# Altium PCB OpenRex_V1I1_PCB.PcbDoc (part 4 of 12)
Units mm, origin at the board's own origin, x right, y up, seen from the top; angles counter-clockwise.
Board outline 70 x 95 mm, 10 copper layers (L1, L2, L3, L4 (PWR), L5 (PWR), L6 (PWR), L7 (PWR), L8, L9, L10), stack 1.632 mm thick; 1080 components, 708 nets, 3831 pads, 2373 vias.
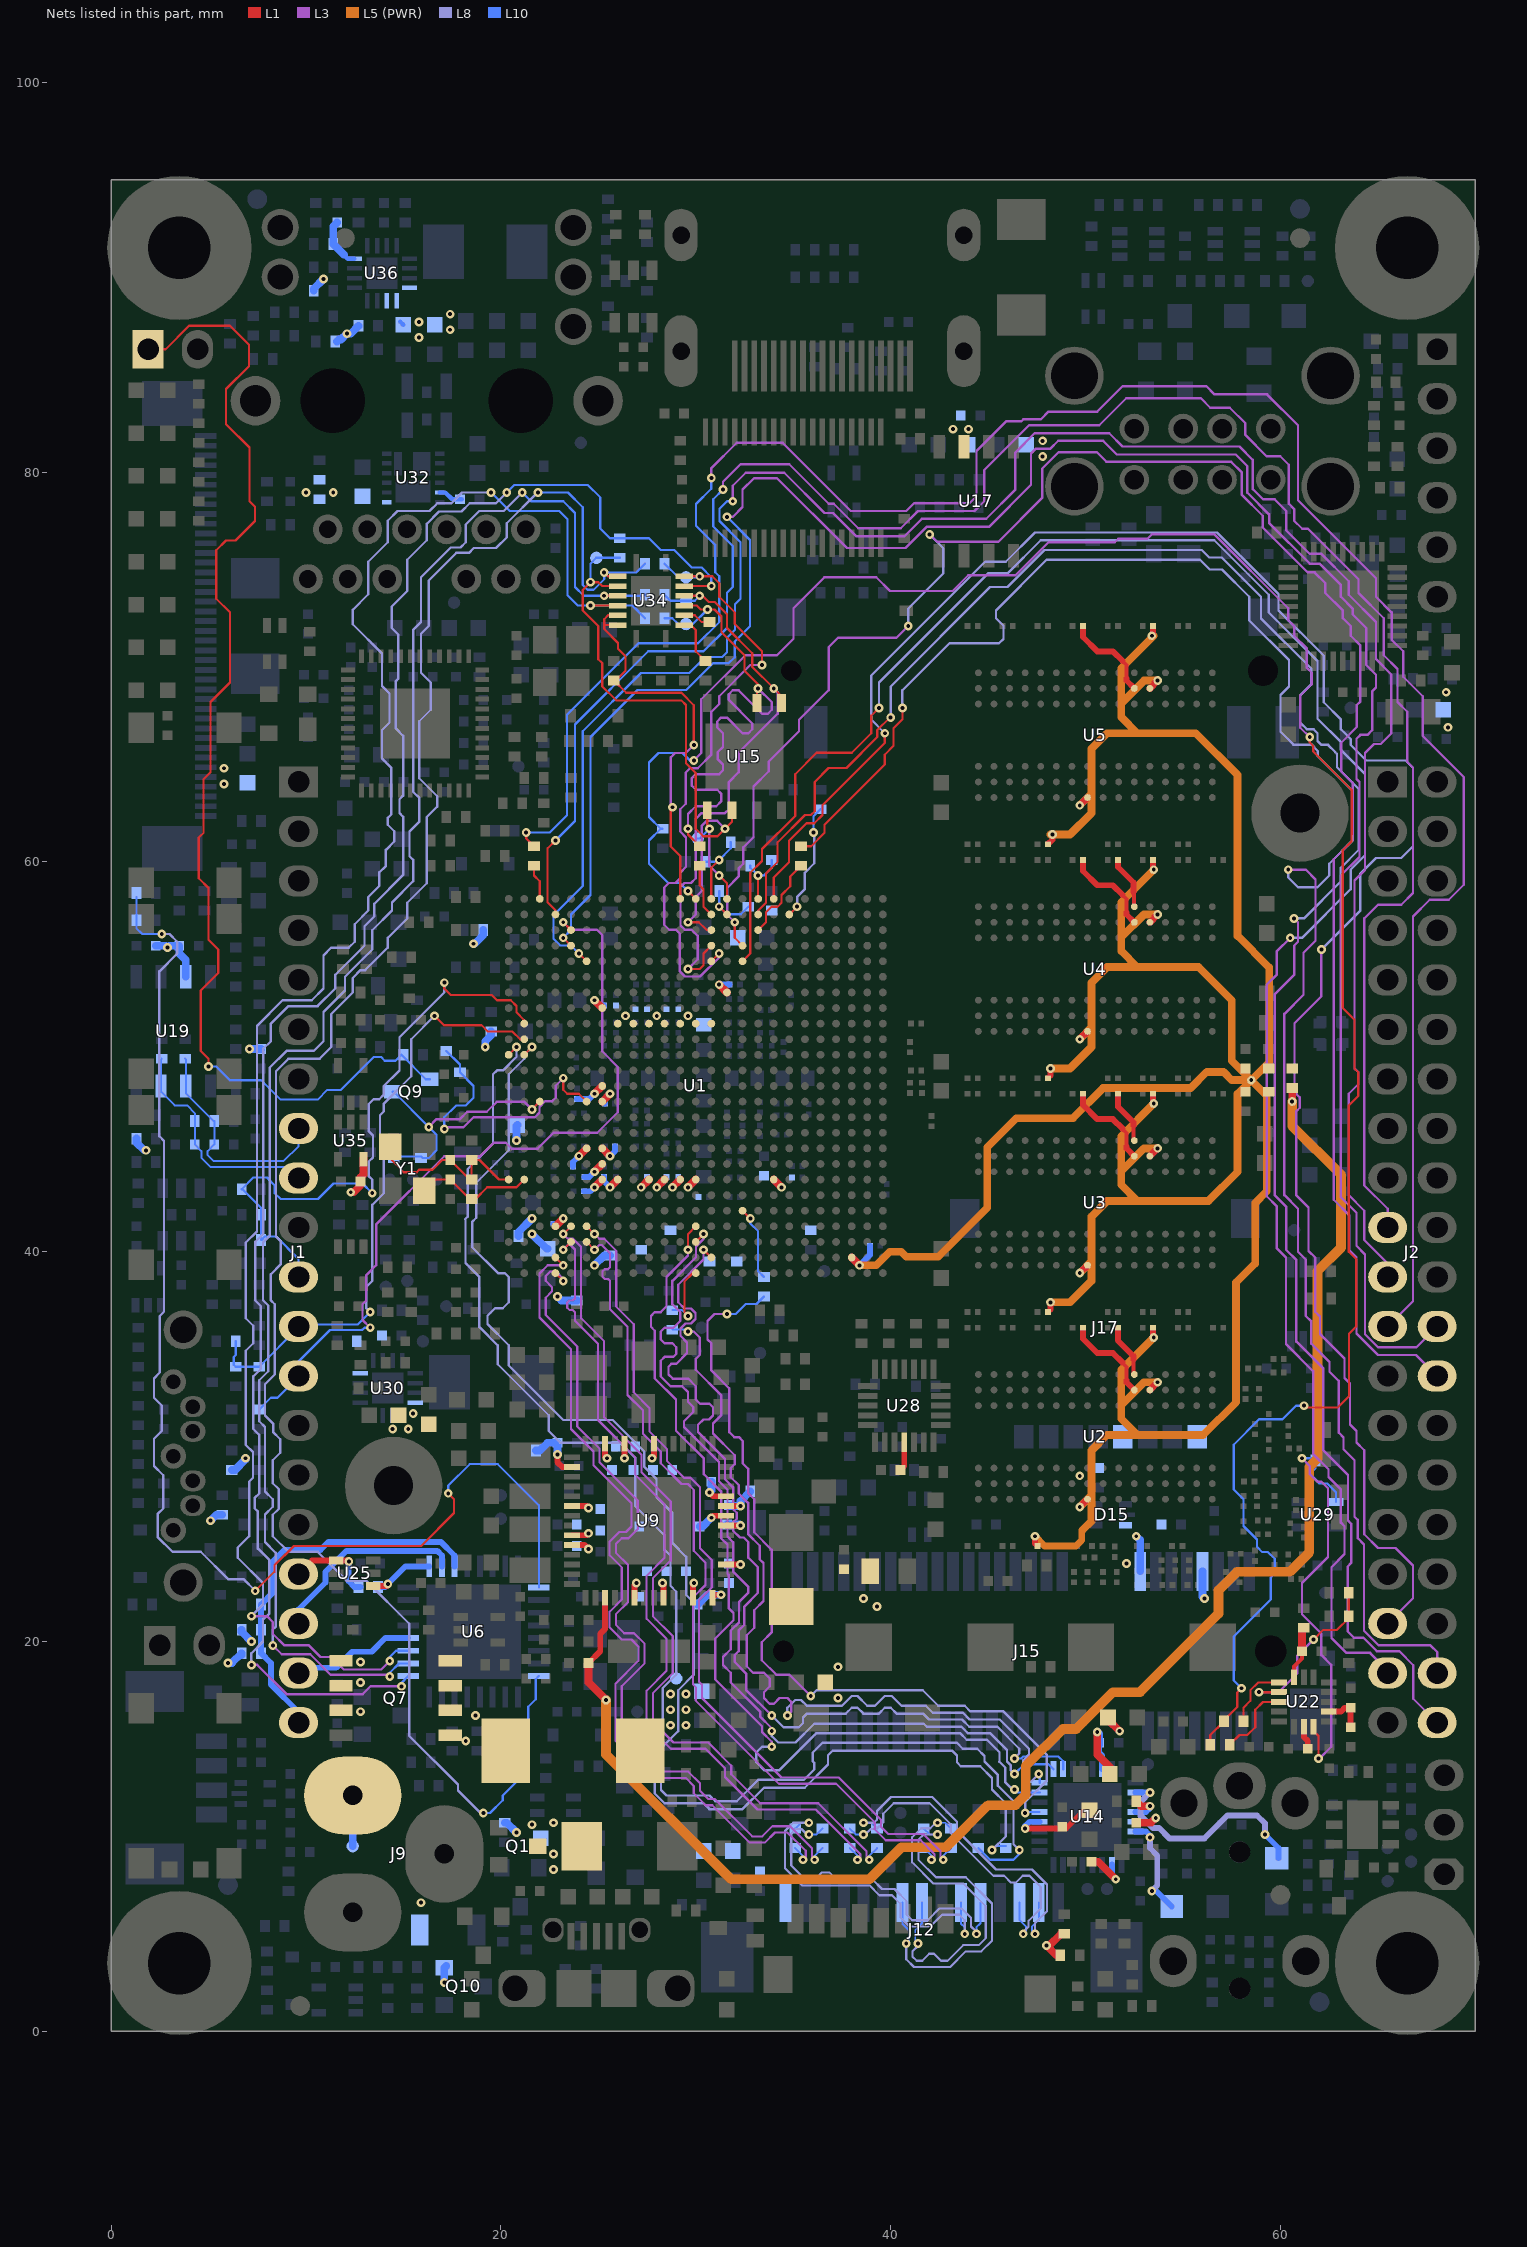
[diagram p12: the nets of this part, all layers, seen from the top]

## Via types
v1: diameter 0.45, hole 0.2, L1 to L10, tented both sides, 2369 vias
v2: diameter 1, hole 0.5, L1 to L10, tented top, 4 vias

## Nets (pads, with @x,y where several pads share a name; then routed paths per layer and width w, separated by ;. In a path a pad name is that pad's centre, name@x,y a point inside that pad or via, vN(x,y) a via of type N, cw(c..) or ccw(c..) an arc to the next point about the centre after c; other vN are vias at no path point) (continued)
+DDR_VREF: C3.1 C4.1 C5.1 C6.1 C7.1 C8.1 C9.1 C10.1 C11.1 C392.2 C393.1 R245.1 R274.2 R345.1 U1.AC2 U2.H1 U2.M8 U3.H1 U3.M8 U4.H1 U4.M8 U5.H1 U5.M8 | length 176.8
  L1 w0.3: v1(47.4,25.4) 47.4,25.035 C4.1@47.535,24.9 ; C5.1@48.065,36.9 48.2,37.035 v1(48.2,37.4) ; C8.1@48.065,48.9 48.2,49.035 v1(48.2,49.4) ; C10.1@48.065,60.9 48.3,61.135 v1(48.3,61.4) ; v1(53.4,71.6) 53.465,71.665 C11.1@53.465,72.1 ; C3.1@53.465,36.1 53.465,35.635 v1(53.5,35.6) ; C6.1@53.465,48.1 53.465,47.635 v1(53.5,47.6) ; C9.1@53.465,60.1 53.465,59.635 v1(53.5,59.6)
  L1 w0.35: v1(49.7,26.9) U2.H1@50.1,27.3 ; v1(49.7,38.9) U3.H1@50.1,39.3 ; v1(49.7,50.9) U4.H1@50.1,51.3 ; v1(49.7,62.9) U5.H1@50.1,63.3 ; U2.M8@53.3,32.9 v1(53.7,33.3) ; U3.M8@53.3,44.9 v1(53.7,45.3) ; U4.M8@53.3,56.9 v1(53.7,57.3) ; U5.M8@53.3,68.9 v1(53.7,69.3)
  L1 w0.4: U1.AC2@38,39.7 v1(38.4,39.3)
  L5 (PWR) w0.35: v1(47.4,25.4) 47.9,24.9 49.507,24.9 49.8,25.193 49.8,25.675 49.825,25.7
  L5 (PWR) w0.4: v1(38.4,39.3) 39.258,39.3 39.958,40 40.54,40 40.8,39.74 42.44,39.74 44.96,42.26 44.96,45.36 46.45,46.85 49.35,46.85 50.9,48.4 55.4,48.4 56.225,49.225 57.075,49.225 57.5,48.8 v1(58.5,48.8) ; v1(48.2,37.4) 49.2,37.4 50.3,38.5 50.3,39.5 ; v1(48.2,49.4) 49.2,49.4 50.3,50.5 50.3,51.5 ; v1@48.2,61.4 49.2,61.4 50.3,62.5 50.3,63.5 ; v1(49.7,26.9) 50.3,27.5 ; v1(49.7,38.9) 50.3,39.5 ; v1(49.7,50.9) 50.3,51.5 ; v1(49.7,62.9) 50.3,63.5 ; 49.825,25.7 50.3,26.175 50.3,27.5 ; v1(53.5,35.6) 51.825,33.925 51.825,32.125 ; v1(53.5,47.6) 51.825,45.925 51.825,44.125 ; v1(53.5,59.6) 51.825,57.925 51.825,56.125 ; v1@53.5,71.6 51.825,69.925 51.825,68.125 ; v1(53.7,33.3) 53,33.3 51.825,32.125 ; v1(53.7,45.3) 53,45.3 51.825,44.125 ; v1(53.7,57.3) 53,57.3 51.825,56.125 ; v1@53.7,69.3 53,69.3 51.825,68.125 ; 50.3,27.5 50.3,29.8 51.1,30.6 52.658,30.6 ; 50.3,39.5 50.3,41.8 51.1,42.6 52.658,42.6 ; 50.3,51.5 50.3,53.8 51.1,54.6 52.658,54.6 ; 50.3,63.5 50.3,65.8 51.1,66.6 52.658,66.6 ; 51.825,32.125 51.825,31.433 52.658,30.6 ; 51.825,44.125 51.825,43.433 52.658,42.6 ; 51.825,56.125 51.825,55.433 52.658,54.6 ; 51.825,68.125 51.825,67.433 52.658,66.6 ; 52.658,30.6 56.042,30.6 57.725,32.283 57.725,38.425 58.7,39.4 58.7,42.5 59.3,43.1 59.3,48 v1(58.5,48.8) ; 52.658,42.6 56.3,42.6 57.8,44.1 57.8,48.1 v1(58.5,48.8) ; 52.658,54.6 55.8,54.6 57.5,52.9 57.5,49.8 v1(58.5,48.8) ; 52.658,66.6 55.658,66.6 57.8,64.458 57.8,56.2 59.425,54.575 59.425,49.725 v1(58.5,48.8)
  L10 w0.3: v1(38.4,39.3) 38.935,39.835 C7.1@38.935,40.3
+DDR_VREF_PMIC: C339.1 R345.2 U9.31 | length 81.6
  L1 w0.3: C339.1@24.5,18.9 25.1,19.5 25.1,20.4 25.35,20.65 U9.31@25.35,22.25
  L1 w0.4: C339.1@24.5,18.9 24.5,17.9 v1(25.4,17) ; v1(60.6,47.7) R345.2@60.6,48.4
  L5 (PWR) w0.5: v1(25.4,17) 25.4,14.2 31.8,7.8 38.913,7.8 40.557,9.443 42.843,9.443 45,11.6 46.4,11.6 46.925,12.125 46.925,13.606 48.834,15.515 49.515,15.515 51.4,17.4 52.8,17.4 56.825,21.425 56.825,22.625 57.775,23.575 60.475,23.575 61.475,24.575 61.475,28.962 61.9,29.387 61.9,39 63.1,40.2 63.1,43.95 60.6,46.45 v1(60.6,47.7)
+GYRO_VREGD: C403.1 U28.16 | length 1.5
  L1 w0.3: C403.1@40.5,28.8 40.7,29 U28.16@40.7,30.225
+HDMI_VP: C76.1 R27.2 U1.L7 | length 0.6
  L1 w0.4: v1(28,43.3) U1.L7@28.4,43.7
+HDMI_VPH: C77.1 R29.2 U1.M7 | length 0.6
  L1 w0.4: v1(28.8,43.3) U1.M7@29.2,43.7
+LVDS_2V5: C79.1 C208.1 R36.2 U1.V7 | length 0.6
  L1 w0.4: U1.V7@34,43.7 v1(34.4,43.3)
+MPCIE_SIM_PWR: C218.1 D15.3 J15.8 J17.C1 | length 1.4
  L10 w0.4: J15.8@56,23.6 56,22.3 v1(56.1,22.2)
  other v1: 52.1,24
+MPCIE_SIM_VPP: C383.1 J15.16 J17.C6 | length 1.9
  L10 w0.4: v1(52.6,25.4) 52.8,25.2 J15.16@52.8,23.6
  other v1: 49.7,28.5
+NVCC_CSI: C145.1 R76.1 U1.N7 | length 0.6
  L1 w0.4: v1(29.6,43.3) U1.N7@30,43.7
+NVCC_ENET: C155.1 C156.1 R74.1 U1.R19 | length 1.1
  L1 w0.4: v1(31.2,53.7) U1.R19@31.6,53.3
  L10 w0.3: v1(31.2,53.7) C155.1@31.735,53.7
+NVCC_MIPI: C149.1 R78.1 U1.K7 | length 0.6
  L1 w0.4: v1(27.2,43.3) U1.K7@27.6,43.7
+NVCC_RGMII: C152.1 R80.1 U1.G18 | length 2.1
  L1 w0.4: v1(24.8,52.9) U1.G18@25.2,52.5
  L10 w0.3: v1(24.8,52.9) 25.065,52.635 C152.1@25.3,52.635
  L10 w0.4: v1(18.6,55.8) 18.658,55.8 19.1,56.242 R80.1@19.1,56.5
+PCIE_VP: C61.1 R13.2 U1.H7 | length 2.3
  L1 w0.4: v1(25.6,43.3) U1.H7@26,43.7
  L10 w0.3: C61.1@25.3,43.835 25.3,43.6 v1(25.6,43.3)
  L10 w0.4: v1(22.9,37.7) 23.1,37.5 R13.2@23.9,37.5
+PCIE_VPH: C64.1 R14.2 U1.G7 | length 2.4
  L1 w0.4: v1(24.8,43.3) U1.G7@25.2,43.7
  L10 w0.3: C64.1@24.265,43.1 24.6,43.1 v1(24.8,43.3)
  L10 w0.4: R14.2@20.9,40.8 20.9,41 v1(21.6,41.7)
+PCIE_VPTX: C62.1 FB1.2 U1.G8 | length 2.3
  L1 w0.4: v1(24.8,44.1) U1.G8@25.2,44.5
  L10 w0.3: C62.1@24.3,43.835 24.535,43.835 v1(24.8,44.1)
  L10 w0.4: v1(21.6,40.9) 22.35,40.15 FB1.2@22.4,40.15
+PMIC_LICELL: C341.1 U9.42 | length 1.9
  L1 w0.3: U9.42@30.85,22.25 31,22.4 v1(31.3,22.4)
  L10 w0.4: C341.1@30.1,21.9 30.6,22.4 v1(31.3,22.4)
+PMIC_VCORE: C379.1 U9.49 | length 1.5
  L1 w0.3: U9.49@31.55,25.95 v1(32.3,25.95)
  L10 w0.4: C379.1@31.6,26 32.25,26 v1(32.3,25.95)
+PMIC_VCOREREF: C378.1 U9.52 | length 1.5
  L1 w0.3: v1(30.7,27.65) 30.9,27.45 U9.52@31.55,27.45
  L10 w0.4: v1(30.7,27.65) 30.8,27.75 C378.1@30.8,28.2
+PWRON_1V375_OPT: C331.1 R341.2 U9.16 | length 3.1
  L1 w0.3: v1(22.9,29.6) 22.9,29.2 23.15,28.95 U9.16@23.65,28.95
  L10 w0.4: R341.2@21.8,29.8 22,29.8 22.4,30.2 C331.1@22.9,30.2 v1(22.9,29.6)
+SATA_VP: C81.1 R18.2 U1.G13 | length 2.6
  L1 w0.4: v1(24.8,48.1) U1.G13@25.2,48.5
  L10 w0.3: C81.1@23.9,47.835 24.535,47.835 v1(24.8,48.1)
  L10 w0.4: v1(24.8,39.3) 25.3,39.8 R18.2@25.6,39.8
+SATA_VPH: C82.1 R19.2 U1.G12 | length 2.1
  L1 w0.4: U1.G12@25.2,47.7 v1(25.6,48.1)
  L10 w0.3: C82.1@25.335,47.6 25.335,47.835 v1(25.6,48.1)
  L10 w0.4: v1(19.2,50.5) 19.2,50.8 19.5,51.1 R19.2@19.5,51.3
+V_INPUT: J9.1 Q7.1 Q7.2 Q7.3 Q10.2 R100.2 R292.2 TP39.1 | length 4.3
  L10 w0.4: TP39.1@12.4,9.5 J9.1@12.4,12.1 ; v1(17.1,2.5) Q10.2@17.1,3.25 Q10.2@17.2,3.35 ; R292.2@20.2,10.7 20.3,10.7 v1(20.8,10.2)
  other v1: 15.9,6.6 12.8,16.4 12.8,17.9 12.8,18.95
+VCC_CAN: C309.2 C397.1 C423.1 FB43.2 FB44.2 R382.2 U19.3 U35.5 | length 6.5
  L1 w0.4: v1(12.3,43.05) 12.45,43.05 12.785,43.385 12.785,43.8 12.95,43.965 U35.5@12.95,44.75
  L10 w0.4: R382.2@1.3,45.8 1.3,45.6 1.7,45.2 v1(1.8,45.2) ; C397.1@2.3,55.7 2.8,55.7 v1(2.9,55.6) 3,55.7 C309.2@3.5,55.7 3.5,55.3 3.835,54.965 U19.3@3.835,54.1 ; v1(7.1,50.4) FB44.2@7.7,50.4
+VCOREDIG: C377.1 R261.2 U9.51 | length 2.3
  L1 w0.3: U9.51@31.55,26.95 v1(32.3,26.95)
  L10 w0.4: C377.1@31.7,26.95 v1(32.3,26.95) 32.3,27.2 R261.2@32.8,27.7
+VDD_CSI: C278.1 C279.1 FB14.2 J12.15 R52.2 R53.2 | length 2.1
  L1 w0.4: R53.2@48.7,3.9 48.5,3.9 v1(48,4.4) 48.142,4.4 48.725,4.983 48.725,5 R52.2@48.9,5
+VDD_SNVS_CAP: C143.1 U1.G9 | length 1.2
  L1 w0.4: U1.G9@25.2,45.3 v1(25.6,44.9)
  L10 w0.3: v1(25.6,44.9) 25.865,45.165 C143.1@25.865,45.4
+VDDA: C283.1 FB13.1 FB26.1 U14.5 | length 3.2
  L1 w0.4: FB26.1@51.15,16.1 51.15,16 v1(51.75,15.4) ; C283.1@52.6,10.7 53.35,10.7 v1(53.6,10.95)
  L10 w0.3: U14.5@52.55,10.75 U14.5@52.56,10.75 53.4,10.75 v1(53.6,10.95)
+VDDD: C282.1 FB11.1 FB20.2 U14.30 | length 4.4
  L1 w0.4: v1(50.6,15.35) 50.6,14.2 51.25,13.55 FB20.2@51.25,13.2
  L10 w0.3: C282.1@50.7,14.7 50.7,14.3 50.85,14.15 U14.30@50.85,13.46 U14.30@50.85,13.45
  L10 w0.4: v1(50.6,15.35) 50.7,15.25 C282.1@50.7,14.8 C282.1@50.7,14.7
+VDDIO: C281.1 FB12.2 U14.20 | length 4.7
  L1 w0.3: v1(46.9,10.4) 49,10.4 49.95,11.35 FB12.2@50.2,11.35
  L10 w0.3: v1(46.9,10.4) 46.9,10.528 47.122,10.75 U14.20@47.65,10.75
+VDDPU: C130.1 C131.1 C132.1 C133.1 C134.1 C135.1 U1.H17 U1.J17 U1.K17 U1.L17 U1.M17 U1.N17 U1.P17
  other v1: 26.4,52.1 28,52.1 29.6,52.1
+VDDUSB: C68.1 C80.1 U1.F9 | length 2
  L1 w0.4: v1(24,44.9) U1.F9@24.4,45.3
  L10 w0.3: C68.1@23.7,44.365 23.7,44.6 v1(24,44.9)
  L10 w0.4: v1(20.8,45.7) 20.8,46.45 C80.1@20.85,46.5
+VIN_4V2: C335.1 C344.1 C345.1 C346.1 C347.1 C348.1 C349.1 C350.1 C351.1 C367.1 C368.1 C369.1 C370.1 C371.1 C372.1 C373.1 C374.1 C375.1 C381.1 C406.1 C407.1 C427.1 C428.1 C435.1 C436.1 D9.1 L11.1 R203.2 R334.2 R335.2 R354.1 R397.2 R398.2 R403.1 TP38.1 U9.7 U9.10 U9.12 U9.20 U9.23 U9.24 U9.34 U9.37 U9.40 U9.45 U9.50 U30.1 U30.2 U30.16 U36.1 U36.2 U36.16 | length 14.8
  L1 w0.3: U9.24@23.65,24.95 24.3,24.95 v1(24.5,24.75) ; U9.23@23.65,25.45 24.4,25.45 v1(24.5,25.55) ; U9.20@23.75,26.95 24.4,26.95 v1(24.5,26.85) ; U9.12@25.35,30.15 25.35,29.5 v1(25.45,29.4) ; v1(26.35,29.4) U9.10@26.35,30.15 ; U9.34@26.85,22.25 26.85,22.9 v1(26.95,23) ; v1(27.75,29.4) 27.85,29.5 U9.7@27.85,30.15 ; v1(28.3,23) 28.35,22.95 U9.37@28.35,22.25 ; U9.40@29.85,22.25 29.85,22.95 v1(29.9,23) ; v1(30.8,26.35) 30.9,26.45 U9.50@31.55,26.45 ; U9.45@31.55,23.95 v1(32.3,23.95)
  L10 w0.23: C427.1@14.85,87.7 C427.1@15,87.55
  L10 w0.4: v1(5.1,26.2) 5.4,26.5 R335.2@5.7,26.5 ; v1(6,18.9) 6.2,18.9 R203.2@6.7,19.4 R203.2@6.7,19.3 ; R334.2@6.2,28.8 6.358,28.8 6.9,29.342 v1(6.9,29.4) ; R397.2@10.4,89.3 10.4,89.4 v1(10.9,89.9) ; R403.1@11.6,86.7 11.7,86.8 11.8,86.8 v1(12.1,87.1) 12.3,87.1 R398.2@12.7,87.5 ; C375.1@30.2,25.9 30.35,25.9 v1(30.8,26.35)
  other v1: 28.7,15.7 29.5,15.7 28.7,16.5 29.5,16.5 28.7,17.3 29.5,17.3 39.3,21.8 38.6,22.2 14.45,30.9 15.25,30.9 15.5,31.7 10,78.95 11.4,78.95 15.8,86.9 17.4,87.3 15.8,87.7 17.4,88.1
+VIN_5V: C88.1 C252.1 D9.2 FB2.1 FB23.1 FB24.2 FB31.2 FB34.2 FB37.1 Q1.3 Q7.5 Q7.6 Q7.7 Q7.8 R365.2 U17.7 | length 0.9
  L1 w0.4: Q1.3@21.9,9.4 Q1.3@21.9,9.5
  L10 w0.4: R365.2@6.7,20.6 6.7,20.5 v1(7.2,20)
  other v1: 22.7,8.3 22.7,9.1 21.6,10.6 22.7,10.7 18.2,14.9 18.7,16.2 37.3,17.1 37.3,18.7 5.8,64 5.8,64.8 68.6,66.9 68.5,68.7 47.8,80.8 47.8,81.6 43.2,82.2 44,82.2
+VIN_ETH: C239.1 R354.2 R355.2 U32.1
ANALOG_IN_0: J1.17 R282.2 U25.1 | length 4.7
  L1 w0.3: J1.17@9.62,23.46 10.31,24.15 v1@12.25,24.15
  L10 w0.3: v1(12.2,24.1) 12.2,24.049 12.18,24.029 12.18,23.1 12.48,22.8 R282.2@12.8,22.8
ANALOG_IN_0_SW: R282.1 U6.25 U25.4 | length 3.8
  L1 w0.3: U25.4@13.45,22.85 v1@14.15,22.85
  L10 w0.3: R282.1@13.7,22.8 14.05,22.8 v1(14.2,22.95) 15.1,23.85 U6.25@16.325,23.85
ANALOG_IN_1: J1.18 U6.26 | length 10.3
  L10 w0.3: J1.18@9.62,20.92 9.62,21.641 11,23.021 11,23.572 12.078,24.65 16.732,24.65 16.975,24.407 U6.26@16.975,23.85
ANALOG_IN_2: J1.19 U6.20 | length 6.4
  L10 w0.3: J1.19@9.62,18.38 9.89,18.65 11.55,18.65 12.375,19.475 13.375,19.475 14.075,20.175 U6.20@15.25,20.175
ANALOG_IN_3: J1.20 R203.1 R239.2 R365.1 U6.27 | length 19.9
  L10 w0.3: J1.20@9.62,15.84 9.62,16.38 8.2,17.8 8.2,18.9 R203.1@7.7,19.4 R365.1@7.7,20.6 R239.2@7.7,21.9 8.3,22.5 8.3,24.1 8.9,24.7 10.749,24.7 11.159,25.11 16.922,25.11 17.625,24.407 U6.27@17.625,23.85
AUD3_CLK: R206.2 U14.21 | length 43.6
  L3 w0.12: v1(31.6,36.8) 30.956,36.8 30.6,36.444 30.6,35.5 30.8,35.3 30.8,33.9 31.715,32.985 31.715,30.741 31.971,30.485 32.215,30.485 32.415,30.285 32.415,29.129 32.685,28.859 32.685,27.615 33,27.3 33,25.6 33.89,24.71 33.89,20.46 33.39,19.96 33.39,19.04 34.13,18.3 34.8,18.3 v1(35.9,17.2)
  L8 w0.12: v1(35.9,17.2) 36.2,17.5 41.644,17.5 42.444,16.7 43.8,16.7 44.085,16.415 45.785,16.415 48,14.2 48,12.848 46.9,11.748 v1(46.9,11.2)
  L10 w0.114: v1(31.6,36.8) 32.056,36.8 32.571,37.315 33.115,37.315 R206.2@33.5,37.7 ; v1(46.9,11.2) 46.95,11.25 U14.21@47.64,11.25
AUD3_CLK_R: R206.1 U1.T5 | length 3.9
  L1 w0.114: U1.T5@32.4,42.1 v1(32.8,41.7)
  L10 w0.114: v1(32.8,41.7) 32.8,41.444 33.2,41.044 33.2,39 R206.1@33.5,38.7
AUD3_RXD: U1.N3 U14.25 | length 50
  L1 w0.114: U1.N3@30,40.5 v1(30.4,40.9)
  L3 w0.12: v1(30.4,40.9) 30.4,40.644 30.015,40.259 30.015,39.715 28.8,38.5 28.8,37.3 29.2,36.9 29.2,36.444 28.856,36.1 28.4,36.1 28.2,35.9 28.2,35.5 28.4,35.3 28.8,35.3 29,35.1 29,34.756 28.844,34.6 28.4,34.6 28.2,34.4 28.2,33.6 28.7,33.1 29.3,33.1 29.6,32.8 29.6,32.3 29.875,32.025 29.875,31.775 29.4,31.3 29.4,31 31.19,29.21 31.19,28.22 31.625,27.785 31.625,25.385 31.915,25.095 31.915,23.591 32.685,22.821 32.685,22.491 32.215,22.021 32.215,20.975 31.8,20.56 31.8,19.6 31.4,19.2 31.4,18.8 31.8,18.4 31.8,17.9 33.3,16.4 33.3,16.152 33.9,15.552 v1(33.9,15.4)
  L8 w0.12: v1(33.9,15.4) 33.9,15.144 34.229,14.815 35.115,14.815 36.08,15.78 41.7,15.78 41.847,15.633 43.623,15.633 43.956,15.3 45.1,15.3 45.965,14.435 45.965,13.841 46.167,13.639 46.167,13.383 v1(46.35,13.2)
  L10 w0.114: v1(46.35,13.2) 46.85,13.7 48.1,13.7 U14.25@48.35,13.45
AUD3_TXC: R124.2 U14.24 | length 43.9
  L3 w0.12: v1(29.6,35.9) 29.9,35.9 30.2,35.6 30.2,34.7 30,34.5 30,33.946 31.3,32.646 31.3,31.6 30.885,31.185 30.885,30.671 32,29.556 32,29.1 31.8,28.9 31.8,28.43 32.205,28.025 32.205,27.589 32.685,27.109 32.685,25.519 33.287,24.917 33.287,24.212 33.475,24.025 33.475,22.075 33,21.6 33,20.7 32.615,20.315 32.615,18.725 32.94,18.4 33.5,18.4 33.8,18.1 33.8,17.7 33.5,17.4 33.5,17.1 33.8,16.8 34,16.8 34.3,17.1 34.7,17.1 34.9,16.9 34.9,16.4 v1(34.7,16.2)
  L8 w0.12: v1(34.7,16.2) 34.7,16.6 35.1,17 35.4,17 35.7,16.7 37.5,16.7 38,17.2 38.3,17.2 38.8,16.7 39.2,16.7 39.7,17.2 40.06,17.2 40.56,16.7 41.8,16.7 42.16,16.34 43.708,16.34 44.048,16 45.6,16 47.1,14.5 47.1,14.2 46.8,13.9 46.8,12.96 46.96,12.8 47.2,12.8 v1(47.6,13.2)
  L10 w0.114: R124.2@28.8,36 29.5,36 v1(29.6,35.9) ; v1(47.6,13.2) 47.65,13.15 U14.24@47.65,12.75
AUD3_TXC_R: R124.1 U1.N1 | length 3.5
  L1 w0.114: v1(29.6,36.7) 29.415,36.885 29.415,38.459 29.856,38.9 U1.N1@30,38.9
  L10 w0.114: R124.1@28.8,37 29.3,37 v1(29.6,36.7)
AUD3_TXD: U1.P2 U14.26 | length 50
  L1 w0.114: v1(30.4,40.1) U1.P2@30.8,39.7
  L3 w0.12: v1(30.4,40.1) 30.4,39.6 29.1,38.3 29.1,37.4 29.415,37.085 29.759,37.085 29.985,36.859 29.985,36.541 29.759,36.315 29.471,36.315 29.215,36.059 29.215,35.681 29.55,35.346 29.55,34.794 29.006,34.25 28.75,34.25 28.6,34.1 28.6,33.7 28.815,33.485 29.615,33.485 30,33.1 30,32.418 30.218,32.2 30.7,32.2 30.885,32.015 30.885,31.6 30.677,31.393 30.392,31.393 30.115,31.115 30.115,30.741 31.5,29.356 31.5,28.32 31.915,27.905 31.915,26.791 32.1,26.606 32.1,26.294 31.915,26.109 31.915,25.685 32.265,25.335 32.459,25.335 32.7,25.094 32.7,24.3 33.185,23.815 33.185,22.485 32.495,21.795 32.495,20.859 32.2,20.564 32.2,19.5 32,19.3 32,18.944 32.585,18.359 32.585,17.515 v1(33.9,16.2)
  L8 w0.12: v1(33.9,16.2) 34.5,15.6 35.3,15.6 35.5,15.8 35.5,16.1 35.7,16.3 37.7,16.3 38,16.6 38.3,16.6 38.6,16.3 39.4,16.3 39.7,16.6 40,16.6 40.3,16.3 41.66,16.3 41.96,16 43.652,16 44.032,15.62 45.48,15.62 46.6,14.5 46.6,14.25 v1(46.35,14)
  L10 w0.114: v1(46.35,14) 46.7,14 46.8,14.1 48.6,14.1 48.85,13.85 U14.26@48.85,13.45
AUD3_TXFS: U1.N4 U14.23 | length 50.1
  L1 w0.114: v1(29.6,40.1) 29.6,40.9 U1.N4@30,41.3
  L3 w0.12: v1(29.6,40.1) 29.6,39.8 28.5,38.7 28.5,37.2 28.2,36.9 27.9,36.9 27.7,36.7 27.7,36.144 27.9,35.944 27.9,33.5 28.985,32.415 28.985,30.815 30.415,29.385 30.415,28.585 31.3,27.7 31.3,25.3 31.625,24.975 31.625,23.475 31.685,23.415 31.685,21.715 31.935,21.465 31.935,21.091 31,20.156 31,18.056 33.4,15.656 33.4,15.356 33.9,14.856 v1(33.9,14.6)
  L8 w0.12: v1(33.9,14.6) 33.4,14.6 33.1,14.3 33.1,13.8 33.5,13.4 34.3,13.4 36.2,15.3 43.56,15.3 43.9,14.96 44.94,14.96 45.585,14.315 45.585,13.841 45.577,13.833 45.887,13.523 45.887,12.769 46.256,12.4 v1(46.35,12.4)
  L10 w0.114: v1(46.35,12.4) 46.5,12.25 U14.23@47.64,12.25 U14.23@47.65,12.25
AUD_HP_L: C290.1 U14.6 | length 5.3
  L8 w0.3: v1(53.3,9.95) 53.3,9.4 53.675,9.025 53.675,7.475 v1(53.4,7.2)
  L10 w0.3: U14.6@52.55,10.25 U14.6@52.56,10.25 53.1,10.25 53.3,10.05 v1(53.3,9.95) ; v1(53.4,7.2) 53.625,7.2 C290.1@54.425,6.4
AUD_HP_R: C291.1 U14.2 | length 11.7
  L8 w0.3: v1(53.3,12.25) 52.825,11.775 52.825,11.053 53.453,10.425 53.775,10.425 54.3,9.9 56.1,9.9 57.275,11.075 58.797,11.075 59.2,10.672 v1(59.2,10.1)
  L10 w0.3: U14.2@52.55,12.25 v1(53.3,12.25) ; v1(59.2,10.1) 59.9,9.4 C291.1@59.9,8.875
AUD_HP_VGND: R234.1 U14.4 | length 1.7
  L1 w0.4: R234.1@52.6,11.8 52.85,11.55 v1(53.3,11.55)
  L10 w0.3: U14.4@52.55,11.25 U14.4@52.56,11.25 53.1,11.25 53.3,11.45 v1(53.3,11.55)
AUD_VAG: C292.1 U14.10 | length 2.5
  L1 w0.4: C292.1@50.3,8.7 50.65,8.7 v1(51.55,7.8)
  L10 w0.3: U14.10@51.35,8.55 U14.10@51.35,8.54 51.35,8 v1(51.55,7.8)
BOARD_ID_1: R346.2 U1.W24 | length 6.2
  L1 w0.114: U1.W24@34.8,57.3 v1(35.2,57.7)
  L8 w0.12: v1(35.2,57.7) 35.2,58.2 35.6,58.6 35.6,59.444 36.08,59.924 36.08,61.458 v1(36.038,61.5) ; v1@36.08,61.5 v1@36.08,61.558
  L10 w0.114: v1(36.038,61.5) 36.038,62.338 R346.2@36.4,62.7
BOARD_VARIANT_0: R15.1 R166.2 U1.P25 | length 4.1
  L1 w0.114: U1.P25@30.8,58.1 30.8,59.7 v1(31.2,60.1)
  L10 w0.114: R166.2@30.5,60 31.1,60 v1(31.2,60.1) 31.8,60.7 R15.1@31.8,61
BOARD_VARIANT_1: R159.1 R164.2 U1.R24 | length 3.3
  L1 w0.114: v1(31.2,57.7) U1.R24@31.6,57.3
  L10 w0.114: R164.2@31.2,58.5 31.2,57.8 v1(31.2,57.7) 31.585,57.315 31.685,57.315 32.315,57.315 R159.1@32.7,57.7 R159.1@32.8,57.7
BOARD_VARIANT_2: R57.1 R163.2 U1.U25 | length 3.1
  L1 w0.114: U1.U25@33.2,58.1 v1(33.2,59.3)
  L10 w0.114: R57.1@32.8,59.8 32.8,59.7 v1(33.2,59.3) 33.5,59.3 33.9,59.7 R163.2@33.9,60.1
BOOT_MODE0: Q9.3 R58.2 R172.1 U1.C12 | length 13
  L1 w0.114: v1(21.6,47.3) U1.C12@22,47.7
  L3 w0.12: v1(16.3,46.4) 16.7,46.8 17.9,46.8 18.28,47.18 19.28,47.18 19.785,47.685 21.215,47.685 v1(21.6,47.3)
  L10 w0.114: Q9.3@14.45,48.2 14.5,48.2 v1(16.3,46.4) 16.7,46 16.7,45.2 16.3,44.8 16,44.8 15.915,44.885 14.585,44.885 R172.1@14.5,44.8
BOOT_MODE1: R171.1 R175.2 U1.F12 | length 15.2
  L1 w0.114: v1(23.2,48.9) 23.2,48.3 23.4,48.1 24,48.1 U1.F12@24.4,47.7
  L3 w0.12: v1(17.1,46.3) 17.185,46.385 18.085,46.385 18.6,46.9 21.744,46.9 21.985,47.141 21.985,47.429 22.271,47.715 22.63,47.715 22.815,47.9 22.815,48.515 v1(23.2,48.9)
  L10 w0.114: v1(17.1,46.3) 17.1,46.894 17.706,47.5 18.2,47.5 18.6,47.9 18.6,48.5 R175.2@17.9,49.2 17.9,49.6 R171.1@17.2,50.3
BOOT_MODE_HDR: JP2.1 Q9.1 R173.1 | length 60.9
  L1 w0.114: JP2.1@1.9,86.3 2.8,86.3 4,87.5 6.1,87.5 7.085,86.515 7.085,85.441 5.9,84.256 5.9,82.456 7.1,81.256 7.1,78.5 7.385,78.215 7.385,77.485 6.385,76.485 5.9,76.485 5.4,75.985 5.4,73.5 6.1,72.8 6.1,69.2 5.1,68.2 5.1,64.6 4.75,64.25 4.75,61.494 4.5,61.244 4.5,59.156 5,58.656 5,56 5.5,55.5 5.5,54.3 4.6,53.4 4.6,50.3 5,49.9 v1(5,49.5)
  L10 w0.114: v1(5,49.5) 5.4,49.5 6.1,48.8 7.7,48.8 8.7,47.8 10.6,47.8 11.1,48.3 11.8,48.3 13.485,49.985 13.859,49.985 14.044,49.8 14.6,49.8 14.9,50.1 16.15,48.85 Q9.1@16.35,48.85
BTN_OR_USER_LED_4: R390.1 R392.1 U6.1 | length 65.8
  L1 w0.114: v1(7.4,22.6) 8.38,23.58 8.38,23.895 9.385,24.9 15.91,24.9 17.6,26.59 17.6,27.3 v1(17.3,27.6)
  L8 w0.12: v1(2.6,56.3) 3,56.3 3.4,55.9 3.4,55.3 2.48,54.38 2.48,45.92 2.715,45.685 2.715,36.915 2.5,36.7 2.5,33.8 2.2,33.5 2.2,32.5 2.6,32.1 2.6,30.8 2.2,30.4 2.2,29 2.675,28.525 2.675,26.82 2.39,26.535 2.39,25.873 2.39,25.359 3.149,24.6 4.6,24.6 6,23.2 6.8,23.2 v1(7.4,22.6)
  L10 w0.114: R392.1@1.3,58.2 R390.1@1.3,57 1.3,56.6 1.6,56.3 v1(2.6,56.3) ; v1(17.3,27.6) 17.3,28 18.4,29.1 19.844,29.1 21.95,26.994 U6.1@21.95,22.775
CAN_N: C312.1 J1.8 R117.2 R249.1 U19.6 | length 11.7
  L10 w0.1: R117.2@3.8,49.9 3.835,49.865 U19.6@3.835,48.5 3.835,48.135 5.27,46.7 R249.1@5.3,46.7 C312.1@5.3,45.5 4.96,45.16 4.96,44.951 5.251,44.66 8.86,44.66 9.62,45.42 J1.8@9.62,46.32
CAN_P: C311.1 J1.9 R41.2 R246.2 U19.7 | length 11.7
  L10 w0.1: R41.2@2.6,49.9 2.565,49.865 U19.7@2.565,48.5 2.565,48.194 3.259,47.5 3.9,47.5 4.3,47.1 R246.2@4.3,46.7 C311.1@4.3,45.5 4.64,45.16 4.64,44.819 5.119,44.34 9.06,44.34 J1.9@9.62,43.78
CFF: C241.2 U32.11 | length 1.3
  L10 w0.22: C241.2@17.9,78.6 C241.2@18,78.6
  L10 w0.23: U32.11@16.86,78.95 17.15,78.95 17.5,78.6 C241.2@17.9,78.6
COMP_1V375: C411.2 R343.2 U30.8
COMP_3V3_HDR: C433.2 R407.2 U36.8 | length 2.6
  L10 w0.23: 11.95,91.15 12.15,90.95 U36.8@12.49,90.95
  L10 w0.4: C433.2@11.6,92.8 11.4,92.6 R407.2@11.4,91.7 11.95,91.15
COMP_BYP: C390.1 C398.1 U22.2 | length 2.4
  L1 w0.3: U22.2@62.275,16.4 U22.2@62.475,16.4 63.1,16.4 63.3,16.6 C390.1@63.6,16.6 C398.1@63.6,15.6
COMP_C1: C391.1 U22.15 | length 1.2
  L1 w0.3: U22.15@61.2,15.625 61.2,15.1 61.4,14.9 C391.1@61.4,14.5
COMP_CRST: C399.1 R110.2 U22.8 | length 2.7
  L1 w0.2: U22.8@60.7,18.175 60.7,18.72 61.1,19.12 C399.1@61.1,19.5 C399.1@61.1,19.6
  L1 w0.4: C399.1@61.1,19.6 61.1,20.6 R110.2@61.2,20.7
COMP_INT: R240.1 R241.2 R242.2 U1.N25 | length 120
  L1 w0.114: v1(29.6,58.5) U1.N25@30,58.1 ; R242.2@56.4,14.7 56.4,15.2 R241.2@57.1,15.9 57.1,15.956 57.785,16.641 57.785,17.385 v1(58,17.6) ; v1(61.2,32.1) 61.3,32 62.935,32 63.515,32.58 63.515,35.786 63.885,36.156 63.885,39.615 63.504,39.996 63.504,47.504 63.985,47.985 63.985,49.2 63.8,49.385 63.8,51.9 63.2,52.5 63.2,60.6 63.64,61.04 63.64,61.378 63.66,61.398 63.66,63.685 61.685,65.66 61.685,65.944 61.5,66.129 v1(61.5,66.4)
  L3 w0.12: v1(29.9,65.2) 30.285,65.585 30.285,68.341 32.544,70.6 34.166,70.6 35.015,71.449 35.015,73.015 36.6,74.6 39.26,74.6 39.96,73.9 43.18,73.9 43.98,74.7 46.4,74.7 48.1,76.4 51.5,76.4 51.675,76.575 53.175,76.575 53.4,76.8 56.61,76.8 60.4,73.01 60.4,72.4 60.7,72.1 60.7,71.6 61.355,70.945 61.355,69.945 61.6,69.7 61.6,69.11 61.015,68.525 61.015,66.885 v1(61.5,66.4)
  L10 w0.114: R240.1@28.3,61.7 R240.1@28.2,61.7 ; v1(29.6,58.5) 29.185,58.915 28.585,58.915 27.6,59.9 27.6,61.1 R240.1@28.2,61.7 ; v1(29.9,65.2) 29.7,65.2 29.315,65.585 28.085,65.585 27.6,65.1 27.6,62.3 R240.1@28.2,61.7 ; v1(58,17.6) 57.6,18 57.6,20.256 59.5,22.156 59.5,23.285 59.7,23.485 59.7,24.244 59.359,24.585 59.071,24.585 58.8,24.856 58.8,25.228 58.1,25.928 58.1,27.3 57.6,27.8 57.6,30.1 58.9,31.4 60.1,31.4 60.8,32.1 v1(61.2,32.1)
COMP_INT1: R242.1 U22.11 | length 3.8
  L1 w0.114: R242.1@57.4,14.7 57.9,15.2 58.3,15.2 58.7,15.6 58.7,16.5 59.1,16.9 U22.11@59.725,16.9
COMP_INT2: R241.1 U22.9 | length 3.2
  L1 w0.114: R241.1@58.1,15.9 58.1,16.6 58.456,16.956 58.456,17.5 58.856,17.9 U22.9@59.725,17.9
COMP_RST: R310.2 U22.16 U29.4 | length 22.9
  L1 w0.114: U22.16@61.7,15.625 61.7,15.4 61.95,15.15 v1(61.95,14)
  L3 w0.12: v1(61.1,29.4) 61.5,29 61.5,28.6 61.9,28.2 62.1,28.2 62.435,27.865 62.435,24.335 61.1,23 61.1,21.4 62.1,20.4 62.1,19.3 62.6,18.8 62.6,14.6 v1@62,14
  L10 w0.114: v1(61.1,29.4) 61.7,29.4 R310.2@61.8,29.3 61.8,28.894 61.665,28.759 61.665,28.435 62,28.1 62.4,28.1 62.85,27.65 U29.4@62.85,27.15
COMP_SA1: R315.1 R316.1 U22.10 | length 8.8
  L1 w0.114: v1(58.9,17.4) U22.10@59.725,17.4 ; v1(61.7,20.1) 62.196,20.596 62.9,20.596 63.5,21.196 R315.1@63.5,21.3 R316.1@63.5,22.5
  L3 w0.12: v1(58.9,17.4) 59.9,17.4 60.86,18.36 60.86,19.26 v1(61.7,20.1)
CPU_GPIO0: J1.11 R208.1 R210.2 R227.2 U1.B17 | length 32.9
  L1 w0.114: v1(17.1,53.8) 17.1,53.5 17.432,53.168 19.532,53.168 19.8,52.9 20.509,52.9 20.8,52.609 20.8,52.28 21.2,51.88 U1.B17@21.2,51.7
  L8 w0.12: v1(13.4,43) 13.4,43.7 13.215,43.885 13.215,44.615 13.436,44.836 13.436,45.964 13.215,46.185 13.215,47.559 13.471,47.815 13.759,47.815 13.985,48.041 13.985,48.485 14.8,49.3 14.8,51 17.1,53.3 v1(17.1,53.8)
  L10 w0.114: J1.11@9.62,38.7 9.62,39.624 8.459,40.785 7.9,40.785 7.715,40.6 R208.1@7.7,40.6 7.7,40.785 R210.2@7.7,41.9 7.7,42.244 6.744,43.2 R227.2@6.7,43.2 7.3,43.8 8,43.8 8.4,43.4 8.4,43 8.7,42.7 10.615,42.7 11.415,43.5 12.9,43.5 v1(13.4,43)
CPU_GPIO1: J1.12 R209.1 R211.2 R228.2 U1.B16 | length 31.5
  L1 w0.114: v1(16.6,52.1) 17.082,51.617 19.013,51.617 19.33,51.3 20.59,51.3 20.99,50.9 U1.B16@21.2,50.9
  L8 w0.12: v1(13.3,36.9) 13.1,37.1 13.1,38.2 13.4,38.5 13.4,42.4 14,43 14,45.8 13.8,46 13.8,47 14,47.2 14,47.6 15.4,49 15.4,50.9 v1(16.6,52.1)
  L10 w0.114: R209.1@6.4,35.4 6.4,34.7 6.3,34.6 6.3,34.2 R211.2@6.4,34.1 R228.2@7.6,34.1 9.62,36.12 J1.12@9.62,36.16 9.72,36.26 12.66,36.26 v1(13.3,36.9)
CPU_GPIO2: J1.13 R273.2 U1.E23 | length 40.9
  L1 w0.114: v1(23.2,56.9) U1.E23@23.6,56.5
  L3 w0.12: v1(13.3,36.1) 12.9,36.5 12.9,37.3 13.1,37.5 13.1,38.8 13.6,39.3 13.6,41.4 17.1,44.9 18.956,44.9 19.641,45.585 20.255,45.585 20.555,45.285 21.885,45.285 22.7,46.1 24.944,46.1 26,47.156 26,49.478 25.2,50.278 25.2,56.244 24.929,56.515 23.585,56.515 v1(23.2,56.9)
  L10 w0.114: R273.2@7.6,31.9 8.2,32.5 8.544,32.5 9.62,33.576 J1.13@9.62,33.62 9.62,34.364 11.236,35.98 12.88,35.98 13,36.1 v1(13.3,36.1)
CPU_XTALI: C83.1 R20.1 R167.1 U1.A7 Y1.3 | length 9
  L1 w0.114: Y1.3@14.325,45.375 14.325,44.775 15.02,44.08 15.68,44.08 15.8,44.2 16.5,44.2 17,44.7 C83.1@17.4,44.7 18.4,43.7 R167.1@18.5,43.7 R20.1@18.5,44.7 18.9,44.7 19.9,43.7 U1.A7@20.4,43.7
CPU_XTALO: C84.1 R167.2 U1.B7 Y1.1 | length 6.2
  L1 w0.114: Y1.1@16.075,43.125 16.65,43.7 C84.1@17.4,43.7 18.4,42.7 R167.2@18.5,42.7 18.7,42.7 19.3,43.3 20.8,43.3 U1.B7@21.2,43.7
CSI_CLK0_N: R125.1 U1.F4 | length 44.5
  L1 w0.1: U1.F4@24.4,41.3 v1(24.8,40.9)
  L3 w0.11: v1(24.8,40.9) 25.04,40.66 25.303,40.66 25.92,40.043 25.92,37.18 26.82,36.28 26.82,32.78 27.62,31.98 27.62,30.78 28.52,29.88 28.52,29.28 29.4,28.4 29.733,28.4 30.22,27.913 30.22,24.78 30.82,24.18 30.82,22.767 30.17,22.117 30.17,17.93 30.32,17.78 30.32,17.098 34.398,13.02 37.333,13.02 39.5,10.853 39.5,10.5 39.88,10.12 41.673,10.12 42.56,9.233 42.56,8.94 v1(42.7,8.8)
  L10 w0.1: v1(42.7,8.8) 42.7,9 R125.1@43.1,9.4
CSI_CLK0_P: R127.1 U1.F3 | length 44.5
  L1 w0.1: U1.F3@24.4,40.5 v1(24.8,40.1)
  L3 w0.11: v1(24.8,40.1) 25.04,40.34 25.17,40.34 25.6,39.91 25.6,39.2 25.5,39.1 25.325,39.1 25.207,38.982 25.207,38.723 25.33,38.6 25.5,38.6 25.6,38.5 25.6,37.047 26.5,36.147 26.5,32.647 27.3,31.847 27.3,30.647 28.2,29.747 28.2,29.147 29.267,28.08 29.6,28.08 29.9,27.78 29.9,24.647 30.5,24.047 30.5,22.9 29.85,22.25 29.85,17.797 30,17.647 30,16.965 34.265,12.7 37.2,12.7 39.18,10.72 39.18,10.367 39.747,9.8 41.54,9.8 42.24,9.1 42.24,8.94 v1(42.1,8.8)
  L10 w0.1: R127.1@41.7,9.4 42.1,9 v1(42.1,8.8)
CSI_CLK0_R_N: J12.8 R125.2 R126.2 | length 17.8
  L8 w0.11: v1(41.4,4.5) 41.4,4.38 41.12,4.1 41.12,3.833 41.333,3.62 41.62,3.62 41.975,3.975 42.225,3.975 42.58,3.62 42.92,3.62 43.72,4.42 44.52,4.42 44.88,4.78 44.88,6.42 43.72,7.58 42.192,7.58 41.1,8.672 41.1,9.953 41.567,10.42 42.027,10.42 42.307,10.7 v1(42.4,10.7)
  L10 w0.1: v1(41.4,4.5) 41.26,4.64 41.26,5.19 41.6,5.53 J12.8@41.6,6.6 ; v1(42.4,10.7) 42.8,10.7 R126.2@43.1,10.4
CSI_CLK0_R_P: J12.9 R127.2 R128.2 | length 17.8
  L8 w0.11: v1(40.8,4.5) 40.8,3.7 41.2,3.3 43.053,3.3 43.853,4.1 44.653,4.1 45.2,4.647 45.2,6.553 43.853,7.9 42.325,7.9 41.42,8.805 41.42,9.82 41.7,10.1 v1(42.4,10.1)
  L10 w0.1: J12.9@40.6,6.6 40.6,5.53 40.94,5.19 40.94,4.64 v1(40.8,4.5) ; R128.2@41.7,10.4 42,10.1 v1(42.4,10.1)
CSI_D0_N: R33.1 U1.E4 | length 44.5
  L1 w0.1: v1(23.2,40.9) U1.E4@23.6,41.3
  L3 w0.11: v1(23.2,40.9) 23.44,40.66 23.703,40.66 24.12,40.243 24.12,36.58 25.3,35.4 25.3,31.5 27.22,29.58 27.22,28.68 28.72,27.18 28.72,24.167 27.8,23.247 27.8,21.3 28.82,20.28 28.82,18.367 27.8,17.347 27.8,15.878 28.858,14.82 30.633,14.82 31.82,13.633 31.82,13.18 33.3,11.7 36.293,11.7 38.76,9.233 38.76,8.94 v1(38.9,8.8)
  L10 w0.1: v1(38.9,8.8) 38.9,9 R33.1@39.3,9.4
CSI_D0_P: R71.1 U1.E3 | length 44.5
  L1 w0.1: v1(23.2,40.1) U1.E3@23.6,40.5
  L3 w0.11: v1(23.2,40.1) 23.44,40.34 23.57,40.34 23.8,40.11 23.8,37.6 23.7,37.5 23.525,37.5 23.407,37.382 23.407,37.123 23.53,37 23.7,37 23.8,36.9 23.8,36.447 24.98,35.267 24.98,31.367 26.9,29.447 26.9,28.547 28.4,27.047 28.4,24.3 27.48,23.38 27.48,21.167 28.5,20.147 28.5,18.5 27.48,17.48 27.48,15.745 28.725,14.5 30.5,14.5 31.5,13.5 31.5,13.047 33.167,11.38 36.16,11.38 38.44,9.1 38.44,8.94 v1(38.3,8.8)
  L10 w0.1: R71.1@37.9,9.4 38.3,9 v1(38.3,8.8)
CSI_D0_R_N: J12.2 R33.2 R65.2 | length 17.8
  L8 w0.11: v1(38.6,10.7) 39.14,10.7 39.3,10.86 39.3,11.3 40.02,12.02 42.133,12.02 43.4,10.753 43.4,10.3 45.4,8.3 47.253,8.3 48.02,7.533 48.02,6.167 47.4,5.547 v1(47.4,5)
  L10 w0.1: v1(38.6,10.7) 39,10.7 R65.2@39.3,10.4 ; v1(47.4,5) 47.26,5.14 47.26,5.38 47.6,5.72 J12.2@47.6,6.6
CSI_D0_R_P: J12.3 R71.2 R119.2 | length 17.8
  L8 w0.11: v1(38.6,10.1) 38.693,10.1 38.973,10.38 39.273,10.38 39.62,10.727 39.62,11.167 40.153,11.7 42,11.7 43.08,10.62 43.08,10.167 45.267,7.98 45.82,7.98 46.175,7.625 46.425,7.625 46.78,7.98 47.12,7.98 47.7,7.4 47.7,6.3 47.08,5.68 47.08,5.373 46.8,5.093 v1(46.8,5)
  L10 w0.1: R119.2@37.9,10.4 38.2,10.1 v1(38.6,10.1) ; J12.3@46.6,6.6 46.6,5.72 46.94,5.38 46.94,5.14 v1(46.8,5)
CSI_D1_N: R120.1 U1.D1 | length 44.5
  L1 w0.1: U1.D1@22.8,38.9 v1(23.2,38.5)
  L3 w0.11: v1(23.2,38.5) 23.2,38.607 22.827,38.98 22.533,38.98 22.3,38.747 22.3,38.5 22.625,38.175 22.625,37.962 22.3,37.637 22.3,36.753 23.92,35.133 23.92,31.033 25.07,29.883 25.07,29.183 27.02,27.233 27.02,25.767 26.553,25.3 26.2,25.3 25.9,25 25.9,24.553 26.52,23.933 26.52,22.02 25.9,21.4 25.9,20.85 26.33,20.42 26.833,20.42 27.375,19.878 27.375,18.875 26.2,17.7 26.2,15.05 27.93,13.32 29.62,13.32 30.22,12.72 30.22,12.343 30.643,11.92 30.98,11.92 32.9,10 33.41,10 33.93,10.52 34.833,10.52 35.96,9.393 35.96,8.94 v1(36.1,8.8)
  L10 w0.1: v1(36.1,8.8) 36.1,9 R120.1@36.5,9.4
CSI_D1_P: R122.1 U1.D2 | length 44.5
  L1 w0.1: U1.D2@22.8,39.7 v1(23.2,39.3)
  L3 w0.11: v1(23.2,39.3) 22.4,39.3 21.98,38.88 21.98,36.62 23.6,35 23.6,30.9 24.75,29.75 24.75,29.05 26.7,27.1 26.7,25.9 26.42,25.62 26.067,25.62 25.58,25.133 25.58,24.42 26.2,23.8 26.2,22.153 25.58,21.533 25.58,20.717 26.197,20.1 26.7,20.1 27.055,19.745 27.055,19.007 25.88,17.833 25.88,14.917 27.797,13 29.487,13 29.9,12.587 29.9,12.21 30.51,11.6 30.847,11.6 32.767,9.68 33.543,9.68 34.063,10.2 34.7,10.2 35.64,9.26 35.64,8.94 v1(35.5,8.8)
  L10 w0.1: R122.1@35.1,9.4 35.5,9 v1(35.5,8.8)
CSI_D1_R_N: J12.5 R120.2 R121.2 | length 17.7
  L8 w0.11: v1(35.8,10.1) 35.707,10.1 35.427,10.38 35.133,10.38 34.9,10.147 34.9,8.503 35.603,7.8 36.12,7.8 36.475,8.155 36.845,8.155 37.2,7.8 39.053,7.8 39.553,7.3 40.2,7.3 40.82,6.68 40.82,5.98 41.1,5.7 41.9,5.7 42.5,6.3 43.653,6.3 44.12,5.833 44.12,5.38 44.4,5.1 v1(44.4,5)
  L10 w0.1: v1(35.8,10.1) 36.2,10.1 R121.2@36.5,10.4 ; v1(44.4,5) 44.4,5.33 44.6,5.53 J12.5@44.6,6.6
CSI_D1_R_P: J12.6 R122.2 R123.2 | length 17.7
  L8 w0.11: v1(35.8,10.7) 35,10.7 34.58,10.28 34.58,8.37 35.47,7.48 38.92,7.48 39.42,6.98 40.067,6.98 40.5,6.547 40.5,5.847 40.967,5.38 42.033,5.38 42.633,5.98 43.52,5.98 43.8,5.7 v1(43.8,5)
  L10 w0.1: R123.2@35.1,10.4 35.4,10.7 v1(35.8,10.7) ; J12.6@43.6,6.6 43.6,5.53 43.8,5.33 v1(43.8,5)
CSI_GPIO0: R129.1 U1.A15 | length 71.9
  L1 w0.114: U1.A15@20.4,50.1 v1(20.8,50.5)
  L8 w0.12: v1(20.8,50.5) 20.8,49.996 20.104,49.3 19.8,49.3 19.6,49.1 19.6,45.544 18.3,44.244 18.3,41.8 18.167,41.668 18.185,41.65 18.185,39.415 18.9,38.7 18.9,36.13 19.84,35.19 19.84,34.222 22.46,31.602 22.46,30.796 23.056,30.2 26.119,30.2 26.9,29.419 26.9,26.956 28.385,25.471 28.385,24.715 28.7,24.4 28.7,22.856 29,22.556 29,18.3 28.3,17.6 28.3,15.3 27.9,14.9 27.9,12.2 28.4,11.7 30.4,11.7 30.7,11.4 32.4,11.4 33.5,12.5 35.59,12.5 36.785,13.695 36.785,14.159 37.025,14.4 37.5,14.4 43.144,14.4 43.4,14.144 43.4,13.8 43.6,13.6 44.6,13.6 45.2,13 45.2,12.4 45.9,11.7 45.9,10 v1(45.2,9.3)
  L10 w0.114: v1(45.2,9.3) 45.4,9.5 R129.1@45.9,9.5
CSI_GPIO1: R136.1 U1.B15 | length 75.4
  L1 w0.114: U1.B15@21.2,50.1 v1(21.6,50.5)
  L8 w0.12: v1(21.6,50.5) 21.2,50.1 21.2,49.9 20.4,49.1 20.4,45.2 18.735,43.535 18.735,41.735 18.525,41.525 18.525,40.231 19.856,38.9 20.2,38.9 20.4,38.7 20.4,37.4 20.1,37.1 19.7,37.1 19.315,36.715 19.315,36.285 20.4,35.2 20.4,34.16 23.2,31.36 25.74,31.36 27.365,29.735 27.365,28.954 27.988,28.332 27.988,27.407 28.8,26.594 28.8,25.056 29.515,24.341 29.515,22.385 29.9,22 29.9,18.3 29.1,17.5 29.1,15.4 28.22,14.52 28.22,12.38 28.5,12.1 30.7,12.1 31,11.8 32.1,11.8 33.2,12.9 35.544,12.9 36.085,13.441 36.085,13.759 36,13.844 36,14.3 36.5,14.8 43.4,14.8 43.7,14.5 44.444,14.5 44.815,14.129 44.815,13.841 45.5,13.156 45.5,12.6 46.3,11.8 46.3,9.6 v1(46.6,9.3)
  L10 w0.114: R136.1@44.5,9.4 45.1,8.8 46.3,8.8 46.6,9.1 v1(46.6,9.3)
CSI_REXT: R160.2 U1.D4 | length 1.2
  L1 w0.4: U1.D4@22.8,41.3 v1(23.2,41.7)
  L10 w0.3: R160.2@22.7,41.435 22.935,41.435 v1(23.2,41.7)
CSPI1_CLK: J2.23 R43.2 | length 115.9
  L1 w0.114: v1(21.3,61.5) 21.3,61.2 R43.2@21.7,60.8
  L3 w0.12: v1(30.8,79.7) 30.8,80.2 32.1,81.5 34.456,81.5 37.956,78 40.8,78 41.2,78.4 44.044,78.4 44.4,78.756 44.4,81.08 45.92,82.6 46.7,82.6 46.8,82.7 47.7,82.7 48.1,83.1 50.6,83.1 51.9,84.4 56.2,84.4 56.615,83.985 59.315,83.985 60.9,82.4 60.9,78.555 64.9,74.555 64.9,73.6 65.7,72.8 65.7,71.4 66.3,70.8 66.3,69.5 67.3,68.5 67.3,66.456 69.4,64.356 69.4,58.822 68.638,58.06 67.66,58.06 66.8,57.2 66.8,37.46 J2.23@65.5,36.16
  L10 w0.114: v1(21.3,61.5) 22.5,61.5 23.4,62.4 23.4,67.556 27.059,71.215 30.115,71.215 31.2,72.3 31.2,74.66 31,74.86 31,76.256 30.015,77.241 30.015,78.359 30.8,79.144 v1(30.8,79.7)
CSPI1_CLK_R: R43.1 U1.C25 | length 1.8
  L1 w0.114: R43.1@21.7,59.8 21.7,59.3 22,59 U1.C25@22,58.1
CSPI1_CS0: J2.24 U1.E22 | length 115.4
  L1 w0.114: v1(23.2,56.1) U1.E22@23.6,55.7
  L3 w0.12: v1(31.6,77.7) 31.9,77.7 32.4,78.2 32.4,79.1 32.985,79.685 34.171,79.685 37.756,76.1 40.756,76.1 41.841,77.185 45.041,77.185 47.2,79.344 47.2,80.944 47.456,81.2 48.2,81.2 48.6,81.6 50.9,81.6 51.6,80.9 57.7,80.9 58.298,80.302 58.298,78.942 59.415,77.825 59.415,77.385 61.5,75.3 62,75.3 63.1,74.2 63.1,73.6 63.7,73 63.7,72.7 64.4,72 64.4,70.1 64.9,69.6 64.9,68.944 64.7,68.744 64.7,66.756 64.459,66.515 64.1,66.515 63.9,66.315 63.9,64.252 64.05,64.102 64.05,60.25 63.093,59.293 63.093,42.807 63.9,42 63.9,40.3 64.34,39.86 64.34,35.76 65,35.1 66.98,35.1 J2.24@68.04,36.16
  L10 w0.114: v1(23.2,56.1) 23.6,56.5 23.6,57.3 24.6,58.3 24.6,66.4 27.015,68.815 29.515,68.815 30.885,70.185 31.685,70.185 32,70.5 32,71.3 32.785,72.085 32.785,76.515 v1(31.6,77.7)
CSPI1_CS1: J2.26 U1.T22 | length 100.9
  L1 w0.114: v1(32,56.9) 32,56.1 U1.T22@32.4,55.7
  L3 w0.12: v1(32,56.9) 31.615,57.285 31.615,58.659 32.2,59.244 32.2,59.66 32.44,59.9 32.44,60.74 32.965,61.265 32.965,63.865 33.745,64.645 33.745,65.145 35.3,66.7 35.3,67.29 36.815,68.805 36.815,71.015 37.3,71.5 40.3,71.5 v1(40.9,72.1) ; v1(42,76.8) 42.385,76.415 45.515,76.415 47.77,78.67 47.77,80.17 48.61,81.01 50.59,81.01 51.068,80.532 57.468,80.532 58.018,79.982 58.018,78.826 59.085,77.759 59.085,77.159 61.394,74.85 61.75,74.85 62.3,74.3 62.3,73.8 63.2,72.9 63.2,72.5 63.6,72.1 63.6,71.6 64.1,71.1 64.1,68.229 63.915,68.044 63.915,66.915 63.115,66.115 63.115,64.641 63.7,64.056 63.7,61.1 62.735,60.135 62.735,42.665 63.54,41.86 63.54,40.06 63.9,39.7 63.9,35.804 65.004,34.7 66.96,34.7 J2.26@68.04,33.62
  L8 w0.12: v1(40.9,72.1) 40.9,73 42.7,74.8 42.7,76.1 v1(42,76.8)
CSPI1_MISO: J2.21 U1.F21 | length 112.1
  L1 w0.114: v1(24,55.3) U1.F21@24.4,54.9
  L3 w0.12: v1(31.9,78.5) 31.9,79.3 32.565,79.965 34.535,79.965 36.6,77.9 37.044,77.9 38.244,76.7 40.7,76.7 41.6,77.6 44.9,77.6 46.4,79.1 46.4,81 47.385,81.985 51.215,81.985 51.892,81.308 57.892,81.308 58.578,80.622 58.578,79.122 59.1,78.6 59.7,78.6 60.3,78 60.3,77 61.5,75.8 62.1,75.8 63.5,74.4 63.5,73.7 64.9,72.3 64.9,70.4 65.685,69.615 65.685,66.585 65.144,66.044 64.8,66.044 64.34,65.584 64.34,59.584 63.8,59.044 63.8,49.4 63.985,49.215 63.985,48.585 63.5,48.1 63.5,42.9 64.3,42.1 64.3,40.6 65.5,39.4 J2.21@65.5,38.7
  L10 w0.114: v1(24,55.3) 23.585,55.715 23.041,55.715 22.7,56.056 22.7,57.256 24.2,58.756 24.2,66.7 27.185,69.685 29.67,69.685 30.5,70.515 31.359,70.515 31.6,70.756 31.6,71.5 32.015,71.915 32.015,73.215 32.3,73.5 32.3,76.4 31.215,77.485 31.215,78.115 31.6,78.5 v1(31.9,78.5)
CSPI1_MOSI: J2.19 U1.D24 | length 109
  L1 w0.114: U1.D24@22.8,57.3 22.8,57.51 22.4,57.91 22.4,60.7 v1(22.8,61.1)
  L3 w0.12: v1(31.4,79.1) 31.4,79.5 32.3,80.4 34.8,80.4 36.822,78.378 37.078,78.378 38.341,77.115 40.515,77.115 41.4,78 44.3,78 44.8,78.5 44.8,80.1 47.1,82.4 50.7,82.4 52.085,83.785 55.915,83.785 56.4,83.3 57.4,83.3 58.2,82.5 58.2,81.9 59.29,80.81 59.99,80.81 60.422,80.378 60.422,78.378 60.7,78.1 60.7,77.5 61.115,77.085 61.415,77.085 64,74.5 64,73.8 65.3,72.5 65.3,70.6 66,69.9 66,68.2 66.5,67.7 66.5,65.126 66.8,64.826 66.8,58.4 66.2,57.8 65,57.8 64.3,57.1 64.3,43.4 65.5,42.2 J2.19@65.5,41.24
  L10 w0.114: v1(22.8,61.1) 23.8,62.1 23.8,67.044 27.556,70.8 30.4,70.8 31.6,72 31.6,73.8 31.9,74.1 31.9,76.2 30.9,77.2 30.9,78.6 v1(31.4,79.1)
CSPI2_CLK: J2.38 R130.2 | length 101.9
  L1 w0.114: R130.2@35.4,60.8 35.919,60.8 36.61,61.49 36.61,61.91 39.7,65 39.7,65.5 40.15,65.95 40.15,66.85 40.6,67.3 v1(40.6,67.9)
  L3 w0.12: v1(60.4,59.6) 61.3,59.6 61.8,59.1 61.8,55.956 61.18,55.336 61.18,53.18 60.2,52.2 60.2,42.9 60.9,42.2 60.9,40 61.3,39.6 61.3,36.7 61.585,36.415 61.585,35.271 62.515,34.341 62.515,33.841 62.985,33.371 62.985,30.715 63.235,30.465 63.235,29.865 63.8,29.3 63.8,26.4 63.962,26.238 63.962,25.303 64.285,24.98 64.285,20.555 65.04,19.8 67.7,19.8 68.04,19.46 J2.38@68.04,18.38
  L8 w0.12: v1(40.6,67.9) 40.6,68.8 43.015,71.215 45.559,71.215 45.785,71.441 45.785,72.115 45.4,72.5 45.4,72.9 48,75.5 55.87,75.5 56.37,75 57,75 58.4,73.6 58.4,72.388 60.435,70.353 60.435,69 60,68.565 60,66.675 60.66,66.015 61.585,66.015 61.915,65.685 61.915,65.43 63.7,63.645 63.7,61.1 62.5,59.9 62.5,59.3 61.9,58.7 60.9,58.7 60.4,59.2 v1(60.4,59.6)
CSPI2_CLK_R: R130.1 U1.U23 | length 4.4
  L1 w0.114: U1.U23@33.2,56.5 33.6,56.9 33.6,57.409 33.891,57.7 34.2,57.7 34.4,57.9 34.4,58.3 34.85,58.75 34.85,59.25 R130.1@35.4,59.8
CSPI2_CS0: J2.35 U1.V25 | length 103.5
  L1 w0.114: U1.V25@34,58.1 34,59.2 34.785,59.985 34.785,61.085 35.685,61.985 36.085,61.985 36.5,62.4 36.5,62.9 39.7,66.1 v1(39.7,66.6)
  L3 w0.12: v1(62.1,55.5) 62.1,53.1 60.715,51.715 60.715,48.185 60.985,47.915 60.985,47.385 60.815,47.215 60.815,42.885 61.44,42.26 61.44,40.041 61.78,39.701 61.78,36.92 62.028,36.672 62.028,35.772 63.285,34.515 63.285,33.515 63.565,33.235 63.565,31.135 63.9,30.8 63.9,30.215 64.3,29.815 64.3,25.5 65,24.8 65.9,24.8 66.8,23.9 66.8,22.22 J2.35@65.5,20.92
  L8 w0.12: v1(39.7,66.6) 39,67.3 39,69.556 44.844,75.4 45.9,75.4 47.4,76.9 56.74,76.9 59.9,73.74 59.9,72.9 62.215,70.585 62.215,68.185 63.1,67.3 63.1,66.8 63.6,66.3 63.6,66 64.4,65.2 66.426,65.2 66.8,64.826 66.8,60.8 66.2,60.2 64.9,60.2 64.1,59.4 64.1,57.5 v1(62.1,55.5) ; v1@62,55.5 v1@62.05,55.55
CSPI2_MISO: J2.40 U1.U24 | length 105.7
  L1 w0.114: U1.U24@33.2,57.3 33.2,57.5 33.6,57.9 33.6,59.4 34.2,60 34.2,61 35.6,62.4 35.9,62.4 36.1,62.6 36.1,64.1 36.815,64.815 37.73,64.815 39.315,66.4 39.315,66.759 39.956,67.4 v1(40,67.4)
  L3 w0.12: v1(60.7,57.1) 60.9,56.9 60.9,55.9 60.7,55.7 60.7,54.2 59.7,53.2 59.7,42.908 60.289,42.319 60.289,40.1 60.815,39.574 60.815,35.385 62.2,34 62.2,29.8 63.46,28.54 63.46,26.205 63.623,26.042 63.623,24.023 63.447,23.847 63.447,20.508 63.756,20.2 64.244,20.2 64.944,19.5 66.1,19.5 66.815,18.785 66.815,17.065 J2.40@68.04,15.84
  L8 w0.12: v1(40,67.4) 40,69 45.1,74.1 46,74.1 47.9,76 55.956,76 56.341,75.615 56.985,75.615 59,73.6 59,72.49 61.585,69.905 61.585,69.125 61,68.54 61,67.156 61.356,66.8 61.7,66.8 61.9,66.6 61.9,66.2 62.1,66 62.444,66 62.81,65.634 62.81,65.624 62.9,65.534 62.9,64.856 64.02,63.736 64.02,60.62 63.1,59.7 63.1,59 61.2,57.1 v1(60.7,57.1)
CSPI2_MOSI: J2.37 U1.T21 | length 106.1
  L1 w0.114: U1.T21@32.4,54.9 32.8,55.3 32.8,59.444 33.4,60.044 33.4,60.656 35.1,62.356 35.1,64.5 36.2,65.6 38,65.6 39,66.6 39,67.5 v1(39.4,67.9)
  L3 w0.12: v1(60.5,56.1) 59.8,55.4 59.8,54.2 59.3,53.7 59.3,42.844 59.8,42.344 59.8,40.193 60.285,39.708 60.285,35.259 61.675,33.869 61.675,29.625 62.465,28.835 62.465,28.435 63.1,27.8 63.1,26.1 63.285,25.915 63.285,24.481 62.615,23.811 62.615,20.185 63.385,19.415 64.6,19.415 65.5,18.515 J2.37@65.5,18.38
  L8 w0.12: v1(39.4,67.9) 39.4,69.2 45,74.8 46,74.8 47.7,76.5 56.6,76.5 59.4,73.7 59.4,72.8 61.9,70.3 61.9,67.344 63.1,66.144 63.1,65.744 64.34,64.504 64.34,60.34 63.6,59.6 63.6,58.6 61.1,56.1 v1(60.5,56.1)
CSPI3_1DIR: R360.1 U34.2 | length 2.5
  L1 w0.114: U34.2@29.4,72.15 29.75,72.15 30,71.9 30,70.8 R360.1@30.5,70.3
CSPI3_2DIR: R359.1 U34.3 | length 1.4
  L1 w0.114: U34.3@29.4,72.65 29.95,72.65 30.3,72.3 R359.1@30.7,72.3
CSPI3_CLK: R131.2 R361.2 TP24.1 U15.6 U34.4 | length 29.8
  L1 w0.114: U34.4@29.4,73.15 30.05,73.15 30.25,72.95 v1(30.6,72.95) 30.958,72.95 31.32,72.588 31.32,71.78 32.5,70.6 32.5,69.8 33.2,69.1 v1(33.2,68.9) 33.135,68.835 U15.6@33.135,68.15 ; v1(29.6,61.7) 29.6,61.4 R131.2@30.2,60.8
  L3 w0.12: v1(29.6,61.7) 29.6,62.456 30,62.856 31.056,62.856 31.3,63.1 31.3,63.5 31.1,63.7 30,63.7 29.8,63.9 29.8,64.3 30,64.5 31.2,64.5 31.4,64.7 31.4,65 31.12,65.28 31.12,65.62 31.4,65.9 31.4,66.6 31.1,66.9 31.1,67.2 31.3,67.4 31.6,67.4 32.4,66.6 32.7,66.6 32.9,66.8 32.9,67.1 31.7,68.3 31.7,68.6 31.9,68.8 32.2,68.8 33.4,67.6 33.7,67.6 33.9,67.8 33.9,68.2 v1(33.2,68.9)
  L10 w0.114: R361.2@28.4,72.5 28.8,72.5 29.1,72.2 TP24.1@29.5,72.2 29.85,72.2 v1(30.6,72.95)
CSPI3_CLK_R: R131.1 U1.P24 | length 2.7
  L1 w0.114: R131.1@30.2,59.8 30.2,58.783 30.4,58.583 30.4,57.7 U1.P24@30.8,57.3
CSPI3_CS0: R364.2 TP25.1 U1.P21 U34.7 | length 31.9
  L1 w0.114: U34.7@29.4,74.65 v1(30.2,74.65) 30.85,74.65 31.2,74.3 31.2,73.6 32,72.8 32,72.2 33.4,70.8 v1(33.4,70.1) ; U1.P21@30.8,54.9 v1(31.2,55.3)
  L3 w0.12: v1(31.2,55.3) 31.2,55.1 30.215,54.115 29.441,54.115 29.185,54.371 29.185,56.315 28.985,56.515 28.641,56.515 28.385,56.771 28.385,58.685 28.615,58.915 28.959,58.915 29.215,59.171 29.215,59.459 29.5,59.744 29.5,61.256 29.2,61.556 29.2,62.7 29.485,62.985 29.485,64.585 29.7,64.8 30.1,64.8 30.8,65.5 30.8,67.7 31.2,68.1 31.2,68.5 32.8,70.1 v1(33.4,70.1)
  L10 w0.114: R364.2@28.4,75.3 29.1,74.6 TP25.1@29.5,74.6 30.15,74.6 v1(30.2,74.65) v1@30.175,74.65
CSPI3_CS2: TP28.1 U1.R25 U15.1 | length 5.8
  L1 w0.114: U15.1@30.595,62.65 30.595,61.805 v1(30.7,61.7) ; v1(31.2,59.3) 31.6,58.9 U1.R25@31.6,58.1
  L3 w0.12: v1(30.7,61.7) 30.7,59.8 v1(31.2,59.3)
  L10 w0.114: TP28.1@30.1,61.2 30.2,61.2 v1(30.7,61.7)
CSPI3_MCU_CLK: R361.1 U6.19 U34.13 | length 94.7
  L1 w0.114: v1(24.6,73.15) U34.13@26,73.15
  L3 w0.12: v1(7.2,21.3) 8,21.3 8.3,21 8.3,20.4 8.9,19.8 10.154,19.8 10.754,19.2 11.3,19.2 11.935,18.565 13.865,18.565 v1(14.3,19)
  L8 w0.12: v1(7.2,21.3) 7.8,21.9 7.8,23 6.5,24.3 6.5,24.815 7.085,25.4 7.085,28.2 7.285,28.4 7.285,29.715 6.915,30.085 6.915,34.915 7.3,35.3 7.3,36.2 6.915,36.585 6.915,40.471 7.485,41.041 7.485,51.585 8.8,52.9 10.3,52.9 10.9,53.5 10.9,55.2 11.3,55.6 12.2,55.6 12.5,55.9 12.5,56.8 13.2,57.5 13.2,58.2 13.765,58.765 13.765,59.459 14.1,59.794 14.1,60.615 14.535,61.05 14.535,61.565 14.2,61.9 14.2,62.256 14.385,62.441 14.385,64.815 13.9,65.3 13.9,66.756 14.285,67.141 14.285,68.643 13.9,69.028 13.9,70.694 12.4,72.194 12.4,72.928 13.2,73.728 13.2,75.4 14.2,76.4 14.2,77.5 14.7,78 16.345,78 16.745,78.4 17.461,78.4 18.011,78.95 v1(19.5,78.95)
  L10 w0.114: v1(14.3,19) 14.3,19.2 14.625,19.525 U6.19@15.25,19.525 ; v1(19.5,78.95) 20.45,78 23,78 23.42,77.58 23.42,73.68 23.95,73.15 v1(24.6,73.15) 26.75,73.15 R361.1@27.4,72.5
CSPI3_MCU_CS0: R364.1 U6.8 U34.10 | length 103.8
  L1 w0.114: v1(25.3,74.85) 25.5,74.65 U34.10@26,74.65
  L8 w0.12: v1(19.1,11.2) 18.956,11.2 17.8,12.356 17.8,12.656 15.3,15.156 15.3,20.91 13.11,23.1 12.1,23.1 10.6,24.6 9.1,24.6 8.3,25.4 8.3,26.5 8.6,26.8 8.6,27.82 8.3,28.12 8.3,29.3 8.685,29.685 8.685,30.375 8.315,30.745 8.315,31.185 7.9,31.6 7.9,33.2 8.4,33.7 8.4,37.3 8.2,37.5 8.2,38.838 8.7,39.338 8.7,40.544 8.46,40.784 8.46,49.26 9.1,49.9 10.7,49.9 11.3,50.5 11.3,52.194 12.4,53.294 12.4,54.044 12.8,54.444 13.044,54.444 14.2,55.6 14.2,56.1 15.2,57.1 15.2,57.9 16.2,58.9 16.2,62.3 16.735,62.835 16.735,63.365 15.815,64.285 15.815,67.215 16.4,67.8 16.4,69.2 15.9,69.7 15.9,71.7 16.3,72.1 16.3,74.437 17.714,75.851 18.365,75.851 18.614,76.1 19.755,76.1 20.3,76.645 20.3,77.377 21.873,78.95 v1(21.9,78.95)
  L10 w0.114: v1(19.1,11.2) 19.444,11.2 20.1,11.856 20.1,12.1 21.4,13.4 21.4,16.656 21.785,17.041 21.785,18.06 U6.8@21.95,18.225 ; v1(21.9,78.95) 23.45,78.95 24.2,78.2 24.2,74.206 24.441,73.965 24.759,73.965 25.3,74.506 v1(25.3,74.85) 26.95,74.85 R364.1@27.4,75.3
CSPI3_MCU_ENN: R319.1 U1.M25 U34.14 U34.15 | length 21
  L1 w0.114: U34.15@26,72.15 25.3,72.15 ; U34.14@26,72.65 25.5,72.65 25.3,72.45 25.3,72.15 ; v1(28.8,62.8) 28.715,62.715 28.715,60.785 29.2,60.3 U1.M25@29.2,58.1 ; v1(29.9,66) 29.9,68.04 29.267,68.674 26.426,68.674 R319.1@25.8,69.3 25.9,69.3 26.4,69.8 26.4,70.556 26.015,70.941 26.015,71.229 25.3,71.944 25.3,72.15
  L3 w0.12: v1(28.8,62.8) 28.715,62.885 28.715,65.359 28.941,65.585 29.485,65.585 v1(29.9,66)
CSPI3_MCU_MISO: R363.1 U6.17 U34.6 | length 94.3
  L1 w0.114: U34.6@29.4,74.15 v1(30.8,74.15)
  L3 w0.12: v1(7.2,18.8) 7.5,18.8 9,17.3 12.914,17.3 13.314,17.7 v1(14.9,17.7)
  L8 w0.12: v1(7.2,18.8) 7.2,19.4 7.8,20 7.8,21.12 8.122,21.442 8.122,24.178 7.535,24.765 7.535,26.665 7.365,26.835 7.365,27.365 7.6,27.6 7.6,30.6 7.3,30.9 7.3,33.6 7.685,33.985 7.685,37.207 7.4,37.492 7.4,40.5 7.81,40.91 7.81,50.41 8.2,50.8 8.2,51.7 9.1,52.6 10.6,52.6 11.5,53.5 11.5,54.2 13,55.7 13,56.7 13.5,57.2 13.5,57.844 14.985,59.329 14.985,62.315 14.8,62.5 14.8,63.215 14.985,63.4 14.985,66.471 14.615,66.841 14.615,69.28 14.735,69.4 14.735,71.665 14.4,72 14.4,73.1 15.2,73.9 15.2,75.5 16.2,76.5 16.2,77.341 16.834,77.975 17.975,77.975 18.4,78.4 19.75,78.4 v1(20.3,78.95)
  L10 w0.114: v1(14.9,17.7) 14.9,17.875 U6.17@15.25,18.225 ; v1(20.3,78.95) 20.685,79.335 24.465,79.335 25.1,78.7 25.1,77.1 25.6,76.6 R363.1@26.1,76.6 27.6,76.6 28.2,76 28.9,76 29.8,75.1 30.3,75.1 30.8,74.6 v1(30.8,74.15)
CSPI3_MCU_MOSI: R362.1 U6.18 U34.12 | length 87.4
  L1 w0.114: v1(25.3,73.65) U34.12@26,73.65
  L3 w0.12: v1(8.3,19.8) 8.76,19.34 10.218,19.34 11.273,18.285 14.215,18.285 v1(14.3,18.2)
  L8 w0.12: v1(8.3,19.8) 8.3,20.6 8.445,20.745 8.445,24.555 7.9,25.1 7.9,26.515 8.3,26.915 8.3,27.3 7.9,27.7 7.9,31 7.6,31.3 7.6,33.4 8.065,33.865 8.065,37.239 7.792,37.512 7.792,40.466 8.135,40.809 8.135,49.435 9,50.3 10.4,50.3 10.9,50.8 10.9,52.3 12,53.4 12,54.1 13.4,55.5 13.4,56.489 14.415,57.504 14.415,57.915 15.5,59 15.5,60.106 15.315,60.291 15.315,61.559 15.82,62.064 15.82,63.28 15.5,63.6 15.5,71.9 15.9,72.3 15.9,74.6 17.431,76.131 17.931,76.131 18.2,76.4 18.2,77.309 18.891,78 20.15,78 v1(21.1,78.95)
  L10 w0.114: v1(14.3,18.2) 14.3,18.4 14.775,18.875 U6.18@15.25,18.875 ; v1(21.1,78.95) 21.55,78.5 23.2,78.5 23.8,77.9 23.8,74.1 24.25,73.65 v1(25.3,73.65) 27.35,73.65 R362.1@27.4,73.7
CSPI3_MISO: R363.2 TP23.1 U1.P23 U15.2 U34.11 | length 32.2
  L1 w0.114: U34.11@26,74.15 25.2,74.15 25,74.35 v1(24.6,74.35) 24.2,73.95 24.2,72.9 25,72.1 25,70.4 25.2,70.2 25.2,69 25.915,68.285 29.259,68.285 29.5,68.044 29.5,65.056 30,64.556 30,61.7 30.385,61.315 31.115,61.315 v1(31.5,61.7) 31.865,62.065 U15.2@31.865,62.65 ; v1(29.6,56.9) 30.16,56.9 30.56,56.5 U1.P23@30.8,56.5
  L3 w0.12: v1(29.6,56.9) 30,57.3 30,58.2 30.315,58.515 30.315,61.859 30.556,62.1 31.1,62.1 v1(31.5,61.7)
  L10 w0.114: v1(24.6,74.35) 24.6,75.3 TP23.1@24.9,75.6 R363.2@26.1,75.6
CSPI3_MOSI: R362.2 TP22.1 U1.P22 U15.5 U34.5 | length 30.6
  L1 w0.114: U34.5@29.4,73.65 30.35,73.65 30.665,73.335 30.969,73.335 31.6,72.704 31.6,72 32.9,70.7 32.9,70 v1(34,68.9) 34.405,68.495 U15.5@34.405,68.15 ; v1(29.6,54.5) 30.2,54.5 30.4,54.7 30.4,55.3 U1.P22@30.8,55.7
  L3 w0.12: v1(29.6,54.5) 30.1,55 30.1,56.2 29.785,56.515 29.441,56.515 29.215,56.741 29.215,58.715 29.415,58.915 29.759,58.915 30,59.156 30,62.2 30.3,62.5 31.5,62.5 31.7,62.7 31.7,64.1 32.2,64.6 32.2,65.6 34.2,67.6 34.2,68.7 v1(34,68.9)
  L10 w0.114: R362.2@28.4,73.7 28.7,73.4 TP22.1@29.5,73.4 29.95,73.4 v1(30.2,73.65)
DRAM0_ZQ: R4.2 U2.L8 | length 4.8
  L1 w0.19: 51.9,34.3 52.1,34.1 52.1,33.4
  L1 w0.3: R4.2@49.865,36.1 49.865,35.535 50.6,34.8 51.4,34.8 51.9,34.3 ; 52.1,33.4 52.1,33.3 U2.L8@52.5,32.9
DRAM0_ZQ1: R306.2 U2.L9 | length 2.7
  L1 w0.19: 52.46,34.46 52.46,33.74 U2.L9@52.5,33.7
  L1 w0.3: R306.2@51.665,36.1 51.665,35.435 52.46,34.64 52.46,34.46
DRAM1_ZQ: R5.2 U3.L8 | length 4.8
  L1 w0.19: 51.9,46.3 52.1,46.1 52.1,45.4
  L1 w0.3: R5.2@49.865,48.1 49.865,47.535 50.6,46.8 51.4,46.8 51.9,46.3 ; 52.1,45.4 52.1,45.3 U3.L8@52.5,44.9
DRAM1_ZQ1: R307.2 U3.L9 | length 2.7
  L1 w0.19: 52.46,46.46 52.46,45.74 U3.L9@52.5,45.7
  L1 w0.3: R307.2@51.665,48.1 51.665,47.435 52.46,46.64 52.46,46.46
DRAM2_ZQ: R8.2 U4.L8 | length 4.8
  L1 w0.19: 51.9,58.3 52.1,58.1 52.1,57.4
  L1 w0.3: R8.2@49.865,60.1 49.865,59.535 50.6,58.8 51.4,58.8 51.9,58.3 ; 52.1,57.4 52.1,57.3 U4.L8@52.5,56.9
DRAM2_ZQ1: R308.2 U4.L9 | length 2.7
  L1 w0.19: 52.46,58.46 52.48,58.44 52.48,57.72 U4.L9@52.5,57.7
  L1 w0.3: R308.2@51.665,60.1 51.665,59.735 52.46,58.94 52.46,58.46
DRAM3_ZQ: R9.2 U5.L8 | length 4.8
  L1 w0.19: 51.9,70.3 52.1,70.1 52.1,69.4
  L1 w0.3: R9.2@49.865,72.1 49.865,71.535 50.6,70.8 51.4,70.8 51.9,70.3 ; 52.1,69.4 52.1,69.3 U5.L8@52.5,68.9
